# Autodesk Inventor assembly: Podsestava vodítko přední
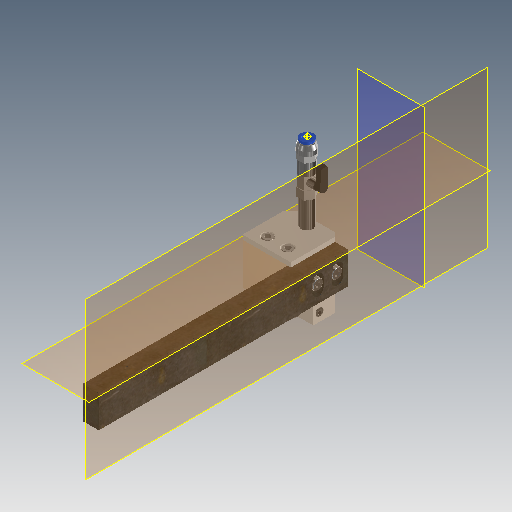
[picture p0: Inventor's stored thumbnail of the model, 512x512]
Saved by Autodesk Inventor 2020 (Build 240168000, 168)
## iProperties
Created: 2025-04
Part Number: Podsestava vodítko přední
Document SubType Name: Assembly
Designer: doma
Mass: 3892.79 g
Surface Area: 1089.82 cm^2
Volume: 502.422 cm^3
Density: 7.74804 g/cm^3
Author: doma
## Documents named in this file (17)
- C:\Users\doma\Desktop\Pásovka záloha\Workgroups\NotInProject\Podsestava vodítko přední.iam
- C:\Users\doma\Desktop\Pásovka záloha\Workgroups\NotInProject\Vedení vodítek pásovina.ipt
- C:\Users\doma\Desktop\Pásovka záloha\Workgroups\NotInProject\Vodítko přední.ipt
- C:\Users\doma\Desktop\Pásovka záloha\Workgroups\NotInProject\Excentr vodících ložisek 1.ipt
- C:\Users\doma\Desktop\Pásovka záloha\Workgroups\NotInProject\Excentr vodících ložisek 2.ipt
- C:\Users\doma\Documents\Inventor\Content Center Files\R2020\cs-CZ\CSN 02 4630\CSN 02 4630 - 609.ipt
- C:\Users\doma\Desktop\Pásovka záloha\Workgroups\NotInProject\Tvrdokovová destička.ipt
- C:\Users\doma\Desktop\Pásovka záloha\Workgroups\NotInProject\Kruhová tvrdokovová destička.ipt
- C:\Users\doma\Desktop\Pásovka záloha\Workgroups\NotInProject\Přechodka.ipt
- C:\Users\doma\Desktop\Pásovka záloha\Workgroups\NotInProject\Trubka chlazení.ipt
- C:\Users\doma\Desktop\Pásovka záloha\Workgroups\NotInProject\Ventil šroubovací.ipt
- C:\Users\doma\Documents\Inventor\Content Center Files\R2020\cs-CZ\ISO 4762(2)\ISO 4762 - M8 x 30ISO.ipt
- C:\Users\doma\Documents\Inventor\Content Center Files\R2020\cs-CZ\ISO 4762(2)\ISO 4762 - M8 x 16ISO.ipt
- C:\Users\doma\Documents\Inventor\Content Center Files\R2020\cs-CZ\CSN 02 1187\CSN 02 1187 - M4 x 0,7 x 16.ipt
- C:\Users\doma\Documents\Inventor\Content Center Files\R2020\cs-CZ\ISO 4762(2)\ISO 4762 - M6 x 20ISO.ipt
- C:\Users\doma\Documents\Inventor\Content Center Files\R2020\cs-CZ\ISO 7380-1\ISO 7380-1 - M6 x 10.ipt
- C:\Users\doma\Documents\Inventor\Content Center Files\R2020\cs-CZ\CSN 02 1703\CSN 02 1703 - 6,4.ipt
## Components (25 placed, 16 different names)
1. Vedení vodítek pásovina:1 — Proti sobě:25, Stejný směr:8, Stejný směr:9
2. Vodítko přední:1 — Proti sobě:19, Proti sobě:20, Úhel:3, Proti sobě:26, Proti sobě:27, Stejný směr:7, Proti sobě:28, Proti sobě:29
3. Excentr vodících ložisek 1:1
4. Excentr vodících ložisek 2:1
5. CSN 02 4630 609:1
6. CSN 02 4630 609:2
7. CSN 02 4630 609:3
8. Tvrdokovová destička:1
9. Tvrdokovová destička:2
10. Kruhová tvrdokovová destička:1
11. Přechodka:1 — Proti sobě:23, Proti sobě:24, Úhel:1, Úhel:2
12. Trubka chlazení:1 — Proti sobě:19, Proti sobě:20, Proti sobě:21, Proti sobě:22, Úhel:1
13. Ventil šroubovací:1 — Proti sobě:21, Proti sobě:22, Proti sobě:23, Proti sobě:24, Úhel:2, Úhel:3
14. ISO 4762 M8 x 30:1
15. ISO 4762 M8 x 30:2
16. ISO 4762 M8 x 16:1 — Stejný směr:4, Proti sobě:25, Proti sobě:26
17. ISO 4762 M8 x 16:2 — Stejný směr:4, Proti sobě:27
18. CSN 02 1187 M4 x 16:1 — Stejný směr:6, Proti sobě:29
19. CSN 02 1187 M4 x 16:2 — Stejný směr:6, Stejný směr:7, Proti sobě:28
20. ISO 4762 M6 x 20:1
21. ISO 4762 M6 x 20:2
22. CSN 02 1703 6,4:1
23. CSN 02 1703 6,4:2
24. ISO 7380-1 M6 x 10:1
25. ISO 7380-1 M6 x 10:2
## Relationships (19: Mate 11, Flush 5, Angle 3)
- Proti sobě:19 [Mate]: Vodítko přední:1 ↔ Trubka chlazení:1
- Proti sobě:20 [Mate]: Vodítko přední:1 ↔ Trubka chlazení:1
- Proti sobě:21 [Mate]: Trubka chlazení:1 ↔ Ventil šroubovací:1
- Proti sobě:22 [Mate]: Trubka chlazení:1 ↔ Ventil šroubovací:1
- Proti sobě:23 [Mate]: Přechodka:1 ↔ Ventil šroubovací:1
- Proti sobě:24 [Mate]: Přechodka:1 ↔ Ventil šroubovací:1
- Úhel:1 [Angle]: Přechodka:1 ↔ Trubka chlazení:1
- Úhel:2 [Angle]: Přechodka:1 ↔ Ventil šroubovací:1
- Úhel:3 [Angle]: Vodítko přední:1 ↔ Ventil šroubovací:1
- Stejný směr:4 [Flush]: ISO 4762 M8 x 16:1 ↔ ISO 4762 M8 x 16:2
- Proti sobě:25 [Mate]: Vedení vodítek pásovina:1 ↔ ISO 4762 M8 x 16:1
- Proti sobě:26 [Mate]: Vodítko přední:1 ↔ ISO 4762 M8 x 16:1
- Proti sobě:27 [Mate]: Vodítko přední:1 ↔ ISO 4762 M8 x 16:2
- Stejný směr:6 [Flush]: CSN 02 1187 M4 x 16:1 ↔ CSN 02 1187 M4 x 16:2
- Stejný směr:7 [Flush]: Vodítko přední:1 ↔ CSN 02 1187 M4 x 16:2
- Proti sobě:28 [Mate]: Vodítko přední:1 ↔ CSN 02 1187 M4 x 16:2
- Proti sobě:29 [Mate]: Vodítko přední:1 ↔ CSN 02 1187 M4 x 16:1
- Stejný směr:8 [Flush]: Vedení vodítek pásovina:1
- Stejný směr:9 [Flush]: Vedení vodítek pásovina:1
